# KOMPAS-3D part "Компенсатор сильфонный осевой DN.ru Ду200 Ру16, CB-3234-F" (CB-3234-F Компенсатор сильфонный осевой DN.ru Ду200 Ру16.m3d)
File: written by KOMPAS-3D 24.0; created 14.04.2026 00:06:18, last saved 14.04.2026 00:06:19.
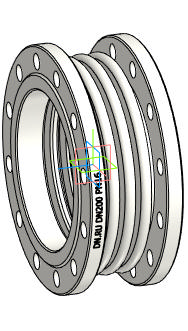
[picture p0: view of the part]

Document properties: Автор: DN.RU; Полное имя файла: D:\PROJECT CAD\DN.RU\...198(ACTUALE). CB-3234-F Компенсатор сильфонный осевой DN.ru\Исходники\DN200\CB-3234-F Компенсатор сильфонный осевой DN.ru Ду200 Ру16.m3d

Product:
- Body: Твердое тело1  | qty 1
    Масса: 22.511516
- Part/product: Компенсатор сильфонный осевой DN.ru Ду200 Ру16  | designation CB-3234-F
    Масса: 18.5
    Раздел спецификации: Прочие изделия
    Комментарий: D140-02119
    Примечание: D140-02119
    additional columns: Типовые

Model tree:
1. Твердое тело1  (labels: Твердое тело1)

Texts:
  CB-3234-F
